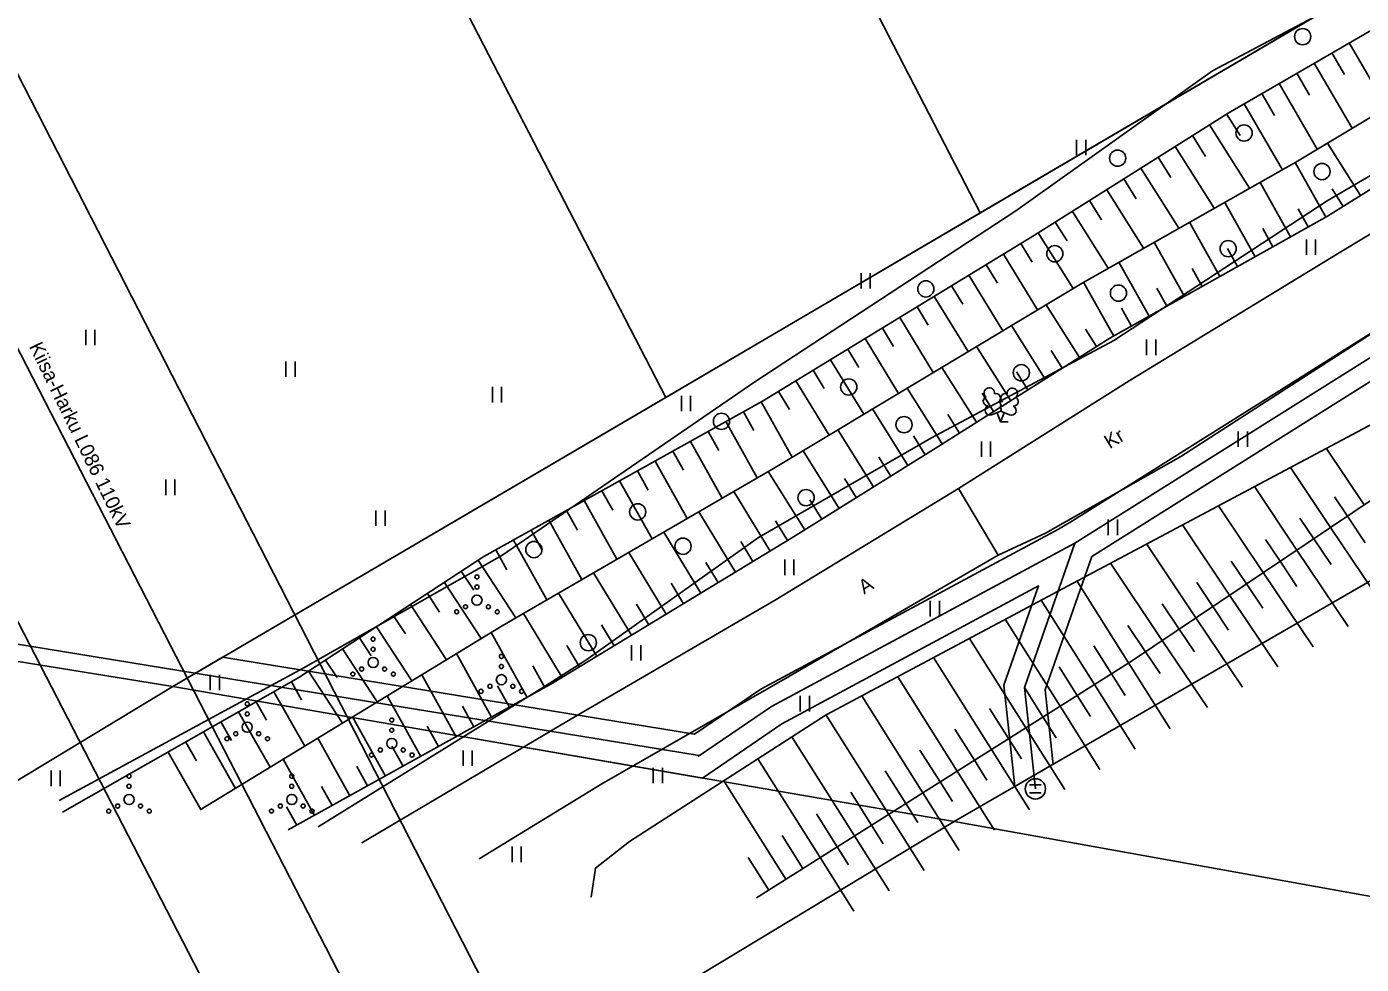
# Model space of a CAD drawing. Extents: x 532656 to 533339, y 6581345 to 6581629.
# Drawn here: x 532719.5 to 532785.3, y 6581439.6 to 6581485.9 of the extents above; entities that cross this region are included whole.
import ezdxf

# ---------------------------------------------------------------- set-up
doc = ezdxf.new("R2010")
doc.units = 0
for name, color, linetype in [('HALJASTUS', 7, 'Continuous'), ('KASUTUSALA', 7, 'Continuous'), ('KPOHULIIN', 7, 'Continuous'), ('PIIR', 7, 'Continuous'), ('PR_SIDE', 7, 'Continuous'), ('PUU', 7, 'Continuous'), ('RELJEEF', 7, 'Continuous'), ('TEE', 7, 'Continuous')]:
    doc.layers.add(name, color=color, linetype=linetype)

msp = doc.modelspace()

# ---------------------------------------------------------------- linework, layer by layer
at = {"layer": 'HALJASTUS'}
for p, q in [((532771.297, 6581480.273), (532771.297, 6581479.512)), ((532771.752, 6581480.273), (532771.752, 6581479.512)), ((532782.638, 6581475.353), (532782.638, 6581474.592)), ((532783.093, 6581475.353), (532783.093, 6581474.592)), ((532760.662, 6581473.696), (532760.662, 6581472.935)), ((532761.117, 6581473.696), (532761.117, 6581472.935)), ((532722.409, 6581470.896), (532722.409, 6581470.135)), ((532722.864, 6581470.896), (532722.864, 6581470.135)), ((532774.746, 6581470.413), (532774.746, 6581469.651)), ((532775.201, 6581470.413), (532775.201, 6581469.651)), ((532732.283, 6581469.334), (532732.283, 6581468.573)), ((532732.738, 6581469.334), (532732.738, 6581468.573)), ((532742.475, 6581468.077), (532742.475, 6581467.316)), ((532742.93, 6581468.077), (532742.93, 6581467.316)), ((532751.801, 6581467.645), (532751.801, 6581466.884)), ((532752.256, 6581467.645), (532752.256, 6581466.884)), ((532779.273, 6581465.882), (532779.273, 6581465.12)), ((532779.728, 6581465.882), (532779.728, 6581465.12)), ((532766.602, 6581465.387), (532766.602, 6581464.626)), ((532767.057, 6581465.387), (532767.057, 6581464.626)), ((532726.354, 6581463.506), (532726.354, 6581462.745)), ((532726.809, 6581463.506), (532726.809, 6581462.745)), ((532736.725, 6581461.986), (532736.725, 6581461.225)), ((532737.18, 6581461.986), (532737.18, 6581461.225)), ((532772.859, 6581461.532), (532772.859, 6581460.771)), ((532773.314, 6581461.532), (532773.314, 6581460.771)), ((532756.896, 6581459.56), (532756.896, 6581458.799)), ((532757.351, 6581459.56), (532757.351, 6581458.799)), ((532764.081, 6581457.52), (532764.081, 6581456.759)), ((532764.536, 6581457.52), (532764.536, 6581456.759)), ((532749.342, 6581455.337), (532749.342, 6581454.576)), ((532749.797, 6581455.337), (532749.797, 6581454.576)), ((532728.549, 6581453.878), (532728.549, 6581453.117)), ((532729.004, 6581453.878), (532729.004, 6581453.117)), ((532757.667, 6581452.833), (532757.667, 6581452.072)), ((532758.122, 6581452.833), (532758.122, 6581452.072)), ((532741.029, 6581450.143), (532741.029, 6581449.382)), ((532741.484, 6581450.143), (532741.484, 6581449.382)), ((532720.7, 6581449.149), (532720.7, 6581448.387)), ((532721.155, 6581449.149), (532721.155, 6581448.387)), ((532750.408, 6581449.286), (532750.408, 6581448.525)), ((532750.863, 6581449.286), (532750.863, 6581448.525)), ((532743.445, 6581445.401), (532743.445, 6581444.64)), ((532743.9, 6581445.401), (532743.9, 6581444.64))]:
    msp.add_line(p, q, dxfattribs=at)
for points in [[(532721.1, 6581447.682), (532733.142, 6581454.211), (532742.937, 6581459.756), (532755.429, 6581468.339), (532768.305, 6581476.764), (532777.997, 6581483.673), (532789.089, 6581489.567), (532799.681, 6581496.557), (532811.18, 6581500.395), (532821.912, 6581506.13), (532827.971, 6581509.845), (532829.953, 6581505.15), (532828.861, 6581503.722), (532825.427, 6581501.661), (532814.712, 6581495.648), (532804.124, 6581488.612), (532793.929, 6581483.263), (532783.661, 6581477.253), (532773.13, 6581470.373), (532764.138, 6581465.563), (532755.607, 6581460.651), (532747.092, 6581454.599)], [(532747.092, 6581454.599), (532744.908, 6581453.22), (532733.873, 6581446.382)]]:
    msp.add_lwpolyline(points, dxfattribs=at)
for centre, radius in [((532782.455, 6581485.361), 0.4), ((532779.563, 6581480.606), 0.4), ((532773.323, 6581479.365), 0.4), ((532783.406, 6581478.704), 0.4), ((532770.224, 6581474.651), 0.4), ((532778.778, 6581474.9), 0.4), ((532763.86, 6581472.915), 0.4), ((532773.364, 6581472.708), 0.4), ((532768.571, 6581468.78), 0.4), ((532760.058, 6581468.077), 0.4), ((532753.777, 6581466.381), 0.4), ((532762.786, 6581466.216), 0.4), ((532757.951, 6581462.618), 0.4), ((532749.645, 6581461.915), 0.4), ((532751.877, 6581460.22), 0.4), ((532744.521, 6581460.055), 0.4), ((532741.713, 6581458.709), 0.1), ((532741.713, 6581458.209), 0.1), ((532741.148, 6581457.234), 0.1), ((532741.713, 6581457.559), 0.25), ((532742.278, 6581457.234), 0.1), ((532740.713, 6581456.984), 0.1), ((532742.713, 6581456.984), 0.1), ((532736.589, 6581455.637), 0.1), ((532736.589, 6581455.137), 0.1), ((532747.207, 6581455.465), 0.4), ((532736.589, 6581454.487), 0.25), ((532742.917, 6581454.787), 0.1), ((532735.589, 6581453.912), 0.1), ((532736.024, 6581454.162), 0.1), ((532737.154, 6581454.162), 0.1), ((532737.589, 6581453.912), 0.1), ((532742.917, 6581454.287), 0.1), ((532742.352, 6581453.312), 0.1), ((532742.917, 6581453.637), 0.25), ((532743.482, 6581453.312), 0.1), ((532741.917, 6581453.062), 0.1), ((532743.917, 6581453.062), 0.1), ((532730.378, 6581452.447), 0.1), ((532730.378, 6581451.947), 0.1), ((532730.378, 6581451.297), 0.25), ((532737.51, 6581451.644), 0.1), ((532729.378, 6581450.722), 0.1), ((532729.813, 6581450.972), 0.1), ((532730.943, 6581450.972), 0.1), ((532731.378, 6581450.722), 0.1), ((532737.51, 6581450.494), 0.25), ((532737.51, 6581451.144), 0.1), ((532736.51, 6581449.919), 0.1), ((532736.945, 6581450.169), 0.1), ((532738.075, 6581450.169), 0.1), ((532738.51, 6581449.919), 0.1), ((532724.546, 6581448.879), 0.1), ((532732.574, 6581448.879), 0.1), ((532724.546, 6581448.379), 0.1), ((532732.574, 6581448.379), 0.1), ((532723.981, 6581447.404), 0.1), ((532724.546, 6581447.729), 0.25), ((532725.111, 6581447.404), 0.1), ((532732.009, 6581447.404), 0.1), ((532732.574, 6581447.729), 0.25), ((532733.139, 6581447.404), 0.1), ((532723.546, 6581447.154), 0.1), ((532725.546, 6581447.154), 0.1), ((532731.574, 6581447.154), 0.1), ((532733.574, 6581447.154), 0.1)]:
    msp.add_circle(centre, radius, dxfattribs=at)
at = {"layer": 'KASUTUSALA'}
msp.add_lwpolyline([(532839.008, 6581499.129), (532800.682, 6581477.703), (532772.047, 6581459.707), (532769.741, 6581453.129), (532770.108, 6581449.749), (532770.14, 6581449.462), (532768.247, 6581448.367), (532768.097, 6581449.749), (532767.704, 6581453.363), (532769.423, 6581458.267), (532756.76, 6581451.463), (532752.836, 6581448.785), (532750.549, 6581449.18), (532745.442, 6581450.061), (532740.99, 6581450.83), (532726.7, 6581453.3), (532729.164, 6581454.745), (532752.451, 6581450.944), (532755.72, 6581453.174), (532770.404, 6581461.065), (532771.095, 6581461.471), (532799.662, 6581479.424), (532838.202, 6581500.971)], dxfattribs=at)
at = {"layer": 'KPOHULIIN'}
for p, q in [((532761.68, 6581400.404), (532685.797, 6581548.327)), ((532685.797, 6581534.575), (532754.855, 6581400.404)), ((532685.797, 6581520.924), (532748.013, 6581400.404))]:
    msp.add_line(p, q, dxfattribs=at)
at = {"layer": 'PIIR'}
for points in [[(532690.736, 6581584.147), (532751.03, 6581467.56), (532726.7, 6581453.3), (532685.797, 6581459.919)], [(532710.965, 6581584.147), (532766.54, 6581476.67), (532751.03, 6581467.56), (532690.736, 6581584.147)], [(532997.696, 6581510.35), (532853.02, 6581527.38), (532766.54, 6581476.67), (532710.965, 6581584.147)], [(532997.696, 6581484.842), (532936.25, 6581492.16), (532895.36, 6581497.07), (532858.61, 6581500.62), (532765.26, 6581446.64), (532740.99, 6581450.83), (532726.7, 6581453.3), (532853.02, 6581527.38), (532997.696, 6581510.35)], [(532685.797, 6581428.571), (532726.7, 6581453.3), (532685.797, 6581459.919)], [(532688.639, 6581400.404), (532765.26, 6581446.64), (532740.99, 6581450.83), (532726.7, 6581453.3), (532685.797, 6581428.571)], [(532688.639, 6581400.404), (532765.26, 6581446.64), (532882.56, 6581425.55), (532934.1, 6581416.97), (532997.696, 6581406.304)]]:
    msp.add_lwpolyline(points, dxfattribs=at)
msp.add_lwpolyline([(532858.61, 6581500.62), (532765.26, 6581446.64), (532882.56, 6581425.55), (532888.42, 6581457.95), (532895.36, 6581497.07)], close=True, dxfattribs=at)
at = {"layer": 'PR_SIDE'}
for p, q in [((532768.976, 6581448.449), (532769.557, 6581448.449)), ((532768.976, 6581448.049), (532769.557, 6581448.049))]:
    msp.add_line(p, q, dxfattribs=at)
for points in [[(532685.797, 6581460.812), (532752.673, 6581449.895), (532752.642, 6581449.863), (532756.241, 6581452.319), (532771.22, 6581460.368), (532800.172, 6581478.564), (532838.605, 6581500.05), (532844.074, 6581501.833), (532856.137, 6581503.74), (532864.294, 6581503.709), (532878.638, 6581501.239), (532905.327, 6581498.018), (532934.766, 6581493.516), (532940.704, 6581499.675), (532975.83, 6581495.548), (532984.66, 6581494.389), (532991.644, 6581492.922), (533009.759, 6581491.731), (533020.322, 6581490.227)], [(532771.22, 6581460.368), (532768.723, 6581453.247), (532769.266, 6581448.249)]]:
    msp.add_lwpolyline(points, dxfattribs=at)
msp.add_circle((532769.266, 6581448.249), 0.5, dxfattribs=at)
at = {"layer": 'PUU'}
for p, q in [((532767.108, 6581466.701), (532767.553, 6581466.876)), ((532767.548, 6581466.366), (532767.373, 6581466.806)), ((532767.548, 6581466.366), (532767.728, 6581466.806)), ((532767.553, 6581466.876), (532767.993, 6581466.696)), ((532767.928, 6581466.366), (532767.548, 6581466.366))]:
    msp.add_line(p, q, dxfattribs=at)
msp.add_lwpolyline([(532767.553, 6581467.371), (532767.533, 6581467.296), (532767.533, 6581467.276), (532767.543, 6581467.246), (532767.563, 6581467.211), (532767.568, 6581467.191), (532767.553, 6581467.156), (532767.528, 6581467.106), (532767.523, 6581467.081), (532767.528, 6581467.066), (532767.538, 6581467.036), (532767.573, 6581466.976), (532767.578, 6581466.956), (532767.573, 6581466.936), (532767.558, 6581466.901), (532767.553, 6581466.876)], dxfattribs=at)
for centre, radius, start, end in [((532766.99, 6581467.78), 0.256, 111.50269, 232.51731), ((532766.99, 6581467.78), 0.256, 350.48556, 111.50017), ((532767.325, 6581467.53), 0.224, 308.50412, 111.57247), ((532767.788, 6581467.525), 0.225, 67.7016, 230.51262), ((532768.126, 6581467.771), 0.256, 67.6168, 188.63142), ((532768.126, 6581467.771), 0.256, 306.59966, 67.61428), ((532766.917, 6581467.369), 0.224, 111.43041, 274.49868), ((532767.021, 6581466.924), 0.237, 111.50143, 291.50036), ((532767.552, 6581467.133), 0.237, 66.76552, 111.50149), ((532768.082, 6581466.916), 0.237, 247.61661, 67.61554), ((532768.194, 6581467.359), 0.224, 264.6183, 67.68657)]:
    msp.add_arc(centre, radius, start, end, dxfattribs=at)
at = {"layer": 'RELJEEF'}
for p, q in [((532784.756, 6581485.059), (532786.605, 6581481.87)), ((532783.891, 6581484.558), (532784.51, 6581483.49)), ((532782.161, 6581483.555), (532782.785, 6581482.478)), ((532783.026, 6581484.056), (532784.891, 6581480.839)), ((532781.296, 6581483.053), (532783.177, 6581479.808)), ((532780.431, 6581482.552), (532781.06, 6581481.465)), ((532779.566, 6581482.05), (532781.453, 6581478.795)), ((532777.856, 6581481.012), (532779.834, 6581477.879)), ((532778.702, 6581481.546), (532779.37, 6581480.488)), ((532777.011, 6581480.478), (532777.661, 6581479.447)), ((532776.165, 6581479.945), (532778.091, 6581476.893)), ((532785.3, 6581477.516), (532783.679, 6581480.111)), ((532775.319, 6581479.411), (532775.953, 6581478.407)), ((532783.602, 6581476.46), (532782.09, 6581479.156)), ((532773.628, 6581478.343), (532774.245, 6581477.367)), ((532774.474, 6581478.877), (532776.349, 6581475.906)), ((532772.783, 6581477.809), (532774.606, 6581474.92)), ((532781.857, 6581475.482), (532780.35, 6581478.171)), ((532784.452, 6581476.986), (532783.909, 6581477.856)), ((532771.937, 6581477.276), (532772.536, 6581476.326)), ((532780.113, 6581474.504), (532778.609, 6581477.186)), ((532771.091, 6581476.742), (532772.864, 6581473.934)), ((532782.73, 6581475.971), (532782.226, 6581476.868)), ((532769.4, 6581475.674), (532771.128, 6581472.937)), ((532770.246, 6581476.208), (532770.828, 6581475.286)), ((532778.368, 6581473.526), (532776.869, 6581476.201)), ((532780.985, 6581474.993), (532780.483, 6581475.888)), ((532768.548, 6581475.151), (532769.108, 6581474.233)), ((532776.624, 6581472.547), (532775.128, 6581475.215)), ((532767.694, 6581474.63), (532769.371, 6581471.881)), ((532779.241, 6581474.015), (532778.74, 6581474.907)), ((532766.841, 6581474.109), (532767.398, 6581473.195)), ((532774.879, 6581471.569), (532773.387, 6581474.23)), ((532777.496, 6581473.036), (532776.997, 6581473.927)), ((532765.133, 6581473.068), (532765.689, 6581472.157)), ((532765.987, 6581473.589), (532767.657, 6581470.851)), ((532773.135, 6581470.591), (532771.647, 6581473.245)), ((532764.279, 6581472.547), (532765.942, 6581469.821)), ((532775.752, 6581472.058), (532775.254, 6581472.947)), ((532763.426, 6581472.027), (532763.979, 6581471.12)), ((532771.437, 6581469.535), (532769.797, 6581472.137)), ((532774.007, 6581471.08), (532773.51, 6581471.966)), ((532762.572, 6581471.506), (532764.228, 6581468.791)), ((532769.745, 6581468.468), (532768.082, 6581471.107)), ((532760.864, 6581470.464), (532762.513, 6581467.761)), ((532761.718, 6581470.985), (532762.269, 6581470.082)), ((532772.283, 6581470.068), (532771.74, 6581470.929)), ((532760.011, 6581469.944), (532760.559, 6581469.044)), ((532768.053, 6581467.402), (532766.367, 6581470.076)), ((532770.591, 6581469.001), (532770.041, 6581469.875)), ((532759.157, 6581469.423), (532760.799, 6581466.731)), ((532758.303, 6581468.902), (532758.849, 6581468.007)), ((532766.361, 6581466.335), (532764.653, 6581469.046)), ((532768.899, 6581467.935), (532768.341, 6581468.82)), ((532756.596, 6581467.861), (532757.14, 6581466.969)), ((532757.45, 6581468.382), (532759.085, 6581465.701)), ((532764.669, 6581465.269), (532762.938, 6581468.016)), ((532767.207, 6581466.869), (532766.641, 6581467.766)), ((532755.741, 6581467.343), (532757.265, 6581464.608)), ((532754.867, 6581466.856), (532755.381, 6581465.935)), ((532762.974, 6581464.208), (532761.234, 6581466.992)), ((532765.515, 6581465.802), (532764.942, 6581466.712)), ((532753.12, 6581465.882), (532753.639, 6581464.951)), ((532753.994, 6581466.369), (532755.543, 6581463.59)), ((532761.278, 6581463.148), (532759.519, 6581465.962)), ((532752.247, 6581465.395), (532753.812, 6581462.588)), ((532763.822, 6581464.738), (532763.245, 6581465.661)), ((532751.374, 6581464.908), (532751.898, 6581463.967)), ((532759.582, 6581462.088), (532757.805, 6581464.932)), ((532762.126, 6581463.678), (532761.543, 6581464.611)), ((532785.493, 6581462.265), (532783.621, 6581465.053)), ((532749.627, 6581463.934), (532750.156, 6581462.984)), ((532750.5, 6581464.421), (532752.081, 6581461.585)), ((532757.886, 6581461.028), (532756.088, 6581463.906)), ((532783.832, 6581461.15), (532781.846, 6581464.109)), ((532748.753, 6581463.447), (532750.351, 6581460.582)), ((532760.43, 6581462.618), (532759.84, 6581463.561)), ((532782.171, 6581460.035), (532780.071, 6581463.165)), ((532747.006, 6581462.473), (532748.62, 6581459.579)), ((532747.88, 6581462.96), (532748.415, 6581462)), ((532756.181, 6581459.983), (532754.394, 6581462.924)), ((532758.734, 6581461.558), (532758.138, 6581462.511)), ((532784.662, 6581461.707), (532784.019, 6581462.665)), ((532746.133, 6581461.986), (532746.674, 6581461.016)), ((532754.471, 6581458.945), (532752.663, 6581461.921)), ((532780.511, 6581458.921), (532778.296, 6581462.221)), ((532745.26, 6581461.499), (532746.889, 6581458.576)), ((532757.035, 6581460.502), (532756.443, 6581461.477)), ((532778.85, 6581457.806), (532776.521, 6581461.276)), ((532783.002, 6581460.593), (532782.321, 6581461.608)), ((532784.662, 6581461.707), (532785.544, 6581460.394)), ((532743.513, 6581460.525), (532745.159, 6581457.573)), ((532744.386, 6581461.012), (532744.932, 6581460.033)), ((532752.762, 6581457.906), (532750.932, 6581460.919)), ((532781.341, 6581459.478), (532780.622, 6581460.55)), ((532783.002, 6581460.593), (532783.858, 6581459.317)), ((532783.832, 6581461.15), (532786.439, 6581457.267)), ((532742.639, 6581460.038), (532743.191, 6581459.049)), ((532751.053, 6581456.868), (532749.201, 6581459.916)), ((532755.326, 6581459.464), (532754.727, 6581460.45)), ((532777.19, 6581456.691), (532774.746, 6581460.332)), ((532782.171, 6581460.035), (532784.701, 6581456.267)), ((532741.778, 6581459.531), (532743.636, 6581456.691)), ((532753.617, 6581458.425), (532753.01, 6581459.424)), ((532775.529, 6581455.577), (532772.971, 6581459.388)), ((532779.681, 6581458.363), (532778.923, 6581459.492)), ((532781.341, 6581459.478), (532782.172, 6581458.241)), ((532740.941, 6581458.984), (532741.551, 6581458.051)), ((532749.343, 6581455.829), (532747.47, 6581458.913)), ((532780.511, 6581458.921), (532782.964, 6581455.266)), ((532739.267, 6581457.889), (532739.866, 6581456.974)), ((532740.104, 6581458.436), (532741.918, 6581455.664)), ((532747.634, 6581454.791), (532745.739, 6581457.91)), ((532751.907, 6581457.387), (532751.294, 6581458.397)), ((532773.866, 6581454.466), (532771.316, 6581458.507)), ((532778.02, 6581457.249), (532777.224, 6581458.434)), ((532779.681, 6581458.363), (532780.486, 6581457.164)), ((532738.431, 6581457.342), (532740.209, 6581454.622)), ((532750.198, 6581456.349), (532749.577, 6581457.37)), ((532772.175, 6581453.399), (532769.547, 6581457.562)), ((532776.359, 6581456.134), (532775.526, 6581457.376)), ((532778.02, 6581457.249), (532778.799, 6581456.088)), ((532778.85, 6581457.806), (532781.227, 6581454.266)), ((532737.594, 6581456.794), (532738.181, 6581455.897)), ((532745.925, 6581453.752), (532744.009, 6581456.907)), ((532770.483, 6581452.331), (532767.778, 6581456.618)), ((532777.19, 6581456.691), (532779.489, 6581453.266)), ((532736.757, 6581456.247), (532738.501, 6581453.581)), ((532744.187, 6581452.763), (532742.411, 6581455.964)), ((532748.489, 6581455.31), (532747.861, 6581456.344)), ((532774.699, 6581455.019), (532773.827, 6581456.318)), ((532776.359, 6581456.134), (532777.113, 6581455.011)), ((532735.92, 6581455.699), (532736.495, 6581454.82)), ((532746.779, 6581454.272), (532746.144, 6581455.317)), ((532768.792, 6581451.264), (532766.009, 6581455.673)), ((532773.02, 6581453.932), (532772.157, 6581455.3)), ((532775.529, 6581455.577), (532777.752, 6581452.265)), ((532734.246, 6581454.605), (532734.81, 6581453.743)), ((532735.083, 6581455.152), (532736.792, 6581452.539)), ((532742.438, 6581451.793), (532740.702, 6581454.923)), ((532767.101, 6581450.196), (532764.241, 6581454.728)), ((532774.699, 6581455.019), (532775.427, 6581453.935)), ((532733.409, 6581454.057), (532735.084, 6581451.498)), ((532745.062, 6581453.248), (532744.464, 6581454.325)), ((532771.329, 6581452.865), (532770.44, 6581454.273)), ((532773.02, 6581453.932), (532773.698, 6581452.859)), ((532773.866, 6581454.466), (532775.921, 6581451.211)), ((532732.559, 6581453.532), (532733.063, 6581452.648)), ((532740.689, 6581450.822), (532738.993, 6581453.881)), ((532743.313, 6581452.278), (532742.727, 6581453.333)), ((532765.409, 6581449.129), (532762.472, 6581453.783)), ((532772.175, 6581453.399), (532774.186, 6581450.212)), ((532731.69, 6581453.037), (532733.216, 6581450.359)), ((532738.941, 6581449.852), (532737.283, 6581452.839)), ((532763.718, 6581448.061), (532760.703, 6581452.838)), ((532769.638, 6581451.798), (532768.723, 6581453.247)), ((532771.329, 6581452.865), (532771.992, 6581451.814)), ((532729.952, 6581452.047), (532731.507, 6581449.317)), ((532730.821, 6581452.542), (532731.335, 6581451.64)), ((532741.564, 6581451.307), (532740.992, 6581452.339)), ((532767.946, 6581450.73), (532767.006, 6581452.22)), ((532770.483, 6581452.331), (532772.451, 6581449.213)), ((532729.083, 6581451.552), (532729.607, 6581450.633)), ((532737.192, 6581448.882), (532735.574, 6581451.797)), ((532739.815, 6581450.337), (532739.256, 6581451.345)), ((532762.027, 6581446.994), (532758.935, 6581451.892)), ((532769.638, 6581451.798), (532770.286, 6581450.77)), ((532728.214, 6581451.057), (532729.799, 6581448.276)), ((532735.443, 6581447.911), (532733.865, 6581450.755)), ((532760.335, 6581445.927), (532757.253, 6581450.81)), ((532766.255, 6581449.663), (532765.289, 6581451.194)), ((532767.946, 6581450.73), (532768.581, 6581449.725)), ((532768.792, 6581451.264), (532770.717, 6581448.214)), ((532726.477, 6581450.067), (532728.09, 6581447.234)), ((532727.346, 6581450.562), (532727.879, 6581449.626)), ((532738.066, 6581449.367), (532737.52, 6581450.35)), ((532764.564, 6581448.595), (532763.572, 6581450.167)), ((532767.101, 6581450.196), (532768.982, 6581447.215)), ((532733.694, 6581446.941), (532732.156, 6581449.713)), ((532736.317, 6581448.396), (532735.785, 6581449.356)), ((532758.644, 6581444.859), (532755.571, 6581449.728)), ((532766.255, 6581449.663), (532766.875, 6581448.68)), ((532756.953, 6581443.792), (532753.89, 6581448.645)), ((532762.872, 6581447.528), (532761.855, 6581449.14)), ((532765.409, 6581449.129), (532767.247, 6581446.217)), ((532734.569, 6581447.426), (532734.049, 6581448.362)), ((532761.181, 6581446.46), (532760.152, 6581448.091)), ((532763.718, 6581448.061), (532765.513, 6581445.218)), ((532764.564, 6581448.595), (532765.169, 6581447.636)), ((532732.82, 6581446.456), (532732.314, 6581447.368)), ((532762.872, 6581447.528), (532763.463, 6581446.591)), ((532759.49, 6581445.393), (532758.464, 6581447.018)), ((532762.027, 6581446.994), (532763.778, 6581444.219)), ((532761.181, 6581446.46), (532761.758, 6581445.547)), ((532757.798, 6581444.325), (532756.776, 6581445.946)), ((532759.49, 6581445.393), (532760.052, 6581444.502)), ((532760.335, 6581445.927), (532762.044, 6581443.22)), ((532756.107, 6581443.258), (532755.088, 6581444.873)), ((532758.644, 6581444.859), (532760.309, 6581442.221))]:
    msp.add_line(p, q, dxfattribs=at)
for points in [[(532721.263, 6581447.097), (532732.92, 6581453.737), (532742.055, 6581459.713), (532755.803, 6581467.377), (532769.218, 6581475.56), (532778.77, 6581481.589), (532790.219, 6581488.226), (532800.366, 6581494.087), (532810.651, 6581500.556), (532821.575, 6581506.794), (532828.134, 6581510.111), (532830.167, 6581509.118), (532831.39, 6581506.051), (532829.967, 6581504.438), (532825.771, 6581501.968), (532815.321, 6581495.209), (532804.525, 6581488.672), (532794.271, 6581483.121), (532783.68, 6581476.504), (532772.937, 6581470.48), (532764.365, 6581465.077), (532757.339, 6581460.687), (532745.444, 6581453.46), (532732.401, 6581446.223)], [(532828.197, 6581506.933), (532813.2, 6581497.948), (532803.475, 6581492.013), (532782.112, 6581479.168), (532771.566, 6581473.2), (532756.345, 6581464.055), (532742.954, 6581456.296), (532728.051, 6581447.21)], [(532872.246, 6581498.47), (532871.331, 6581499.421), (532869.589, 6581500.574), (532857.082, 6581499.821), (532842.776, 6581496.668), (532831.067, 6581490.625), (532821.585, 6581485.149), (532803.655, 6581474.2), (532788.457, 6581467.626), (532771.369, 6581458.536), (532758.947, 6581451.9), (532749.245, 6581445.656), (532747.562, 6581444.346), (532747.354, 6581442.902)], [(532869.486, 6581498.095), (532849.026, 6581494.011), (532833.913, 6581486.71), (532824.11, 6581481.518), (532807.265, 6581472.455), (532790.383, 6581465.547), (532774.009, 6581454.556), (532755.51, 6581442.881)]]:
    msp.add_lwpolyline(points, dxfattribs=at)
at = {"layer": 'TEE'}
for points in [[(532828.292, 6581513.296), (532832.02, 6581512.679), (532836.397, 6581511.316), (532840.31, 6581509.519), (532840.891, 6581508.347), (532840.082, 6581506.769), (532836.051, 6581504.503), (532826.569, 6581499.82), (532816.225, 6581493.907), (532805.282, 6581487.21), (532795.313, 6581481.353), (532784.256, 6581474.69), (532773.891, 6581468.38), (532765.47, 6581463.073)], [(532767.433, 6581459.775), (532769.763, 6581460.862), (532776.446, 6581464.64), (532786.616, 6581471.204), (532796.99, 6581477.695), (532807.38, 6581484.085), (532818.009, 6581490.276), (532828.082, 6581495.934), (532837.804, 6581500.488), (532846.951, 6581503.331), (532856.666, 6581504.417), (532863.379, 6581504.434), (532873.451, 6581503.101), (532883.953, 6581501.601), (532885.768, 6581500.904), (532886.826, 6581499.461), (532886.304, 6581496.797)], [(532765.47, 6581463.073), (532756.48, 6581457.593), (532746.586, 6581451.843), (532736.029, 6581445.585)], [(532741.815, 6581444.798), (532747.871, 6581448.494), (532757.129, 6581453.812), (532767.433, 6581459.775), (532765.47, 6581463.073)]]:
    msp.add_lwpolyline(points, dxfattribs=at)

# ---------------------------------------------------------------- texts
at = {"layer": 'KPOHULIIN'}
msp.add_text('Kiisa-Harku L086 110kV', height=0.7, rotation=295.9838, dxfattribs=at).set_placement((532719.596, 6581470.081))
at = {"layer": 'TEE'}
for s, rotation, p in [('Kr', 31.43586, (532772.932, 6581465.002)), ('A', 31.77073, (532760.814, 6581457.832))]:
    msp.add_text(s, height=0.7, rotation=rotation, dxfattribs=at).set_placement(p)

doc.saveas('drawing.dxf')
